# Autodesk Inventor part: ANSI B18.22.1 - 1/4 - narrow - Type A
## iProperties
Comments: To add or edit properties for Autodesk Inventor files, use iProperties.
Created: 2004-12
Part Number: ANSI B18.22.1 - 1/4 - narrow - Type A
Vendor: Autodesk Inc.
Document SubType Name: Modeling
Designer: John Blackburn
Material: Default
Description: Washer A
Standard: ANSI B18.22.1
Alert: To add or edit properties for Autodesk Inventor files, use iProperties.
Control State: 0
Master: False
Checked Out: False
Shininess: 64.0
Length Units: 11272
Angle Units: 11279
Time Units: 11290
Mass Units: 11286
Length Display Precision: 3
Angle Display Precision: 2
Compacted: True
Classification: un/spsc 31161807
Density: 0.0
Volumn: 0.0
Area: 0.0
PropertySet Name: Model Information
Author: John Blackburn
Revision Number: 8
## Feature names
1. Body [Extrusion]
